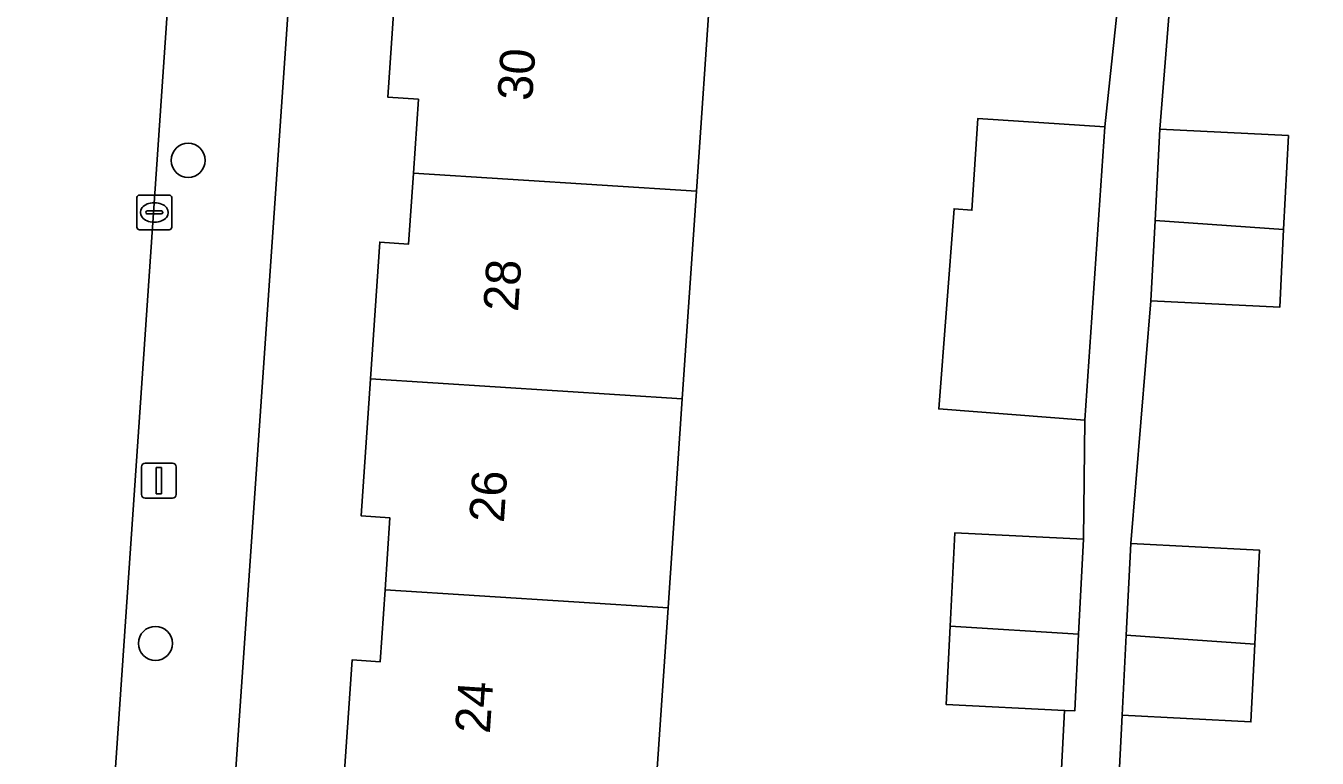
# Model space of a CAD drawing. Extents: x 161848 to 162726, y 385382 to 386521.
# Drawn here: x 162163.48 to 162200.55, y 385538.06 to 385559.08 of the extents above; entities that cross this region are included whole.
import ezdxf

# ---------------------------------------------------------------- set-up
doc = ezdxf.new("R2010")
doc.units = 0
for name, color, linetype in [('IMGEO_Boom', 7, 'Continuous'), ('IMGEO_Erf', 7, 'Continuous'), ('IMGEO_Kolk', 7, 'Continuous'), ('IMGEO_Lichtmast', 7, 'Continuous'), ('IMGEO_Pand', 7, 'Continuous'), ('IMGEO_Pand_nummerreeks', 7, 'Continuous'), ('IMGEO_Rijbaan_lokaal_open', 7, 'Continuous'), ('IMGEO_Voetpad_open', 7, 'Continuous')]:
    doc.layers.add(name, color=color, linetype=linetype)

msp = doc.modelspace()

# ---------------------------------------------------------------- linework, layer by layer
at = {"layer": 'IMGEO_Boom'}
for centre in [(162168.143, 385555.222), (162167.204, 385541.354)]:
    msp.add_circle(centre, 0.489, dxfattribs=at)
at = {"layer": 'IMGEO_Erf'}
for points in [[(162172.594, 385537.139), (162172.849, 385540.88), (162173.652, 385540.825), (162173.793, 385542.892), (162173.934, 385544.958), (162173.109, 385545.015), (162173.377, 385548.946), (162173.644, 385552.875), (162174.469, 385552.819), (162174.608, 385554.855), (162174.752, 385556.977), (162173.874, 385557.037), (162174.143, 385560.983), (162174.411, 385564.925), (162175.255, 385564.868), (162175.394, 385566.905), (162175.534, 385568.968), (162174.708, 385569.025), (162174.97, 385572.867), (162175.556, 385572.827), (162175.575, 385573.109), (162178.486, 385572.911), (162178.639, 385575.119), (162174.67, 385575.382)], [(162220.438, 385572.152), (162212.706, 385572.714), (162200.83, 385573.578), (162200.822, 385573.464), (162200.682, 385571.384), (162200.268, 385565.225), (162200.114, 385562.932), (162196.598, 385563.182), (162196.031, 385556.12), (162199.725, 385555.932), (162199.587, 385553.241), (162199.473, 385551.003), (162195.779, 385551.192), (162195.203, 385544.218), (162198.897, 385544.03), (162198.759, 385541.335), (162198.645, 385539.101), (162194.951, 385539.29), (162194.76, 385535.529)], [(162171.93, 385572.873), (162166.909, 385500)], [(162183.142, 385560.377), (162182.731, 385554.339), (162182.324, 385548.374), (162181.916, 385542.371), (162181.497, 385536.226)], [(162193.033, 385534.21), (162193.3, 385539.431), (162189.897, 385539.605), (162190.012, 385541.852), (162190.149, 385544.533), (162193.843, 385544.344), (162193.881, 385547.762), (162189.688, 385548.084), (162190.128, 385553.83), (162190.638, 385553.79), (162190.812, 385556.427), (162194.451, 385556.187), (162194.817, 385559.603)]]:
    msp.add_lwpolyline(points, dxfattribs=at)
at = {"layer": 'IMGEO_Kolk'}
for p, q in [((162166.671, 385553.3), (162166.671, 385554.152)), ((162166.746, 385554.226), (162167.598, 385554.226)), ((162167.159, 385554.006), (162167.184, 385554.006)), ((162167.672, 385554.152), (162167.672, 385553.3)), ((162166.93, 385553.72), (162166.93, 385553.732)), ((162167.368, 385553.683), (162166.97, 385553.683)), ((162166.973, 385553.769), (162167.371, 385553.769)), ((162167.414, 385553.732), (162167.414, 385553.72)), ((162167.598, 385553.226), (162166.746, 385553.226)), ((162167.182, 385553.446), (162167.157, 385553.446))]:
    msp.add_line(p, q, dxfattribs=at)
for points in [[(162166.671, 385553.3), (162166.671, 385554.152)], [(162166.746, 385554.226), (162167.598, 385554.226)], [(162167.672, 385554.152), (162167.672, 385553.3)], [(162167.598, 385553.226), (162166.746, 385553.226)]]:
    msp.add_lwpolyline(points, dxfattribs=at)
for centre, radius, start, end in [((162166.748, 385554.15), 0.0765, 91.552, 178.448), ((162166.748, 385554.15), 0.0765, 91.552, 178.448), ((162167.596, 385554.15), 0.0765, 1.552, 88.448), ((162167.596, 385554.15), 0.0765, 1.552, 88.448), ((162166.97, 385553.729), 0.0403, 85.8775, 175.7526), ((162166.967, 385553.719), 0.0366, 178.938, 274.7102), ((162167.371, 385553.726), 0.043, 264.8664, 352.4533), ((162167.375, 385553.731), 0.0386, 1.7309, 96.639), ((162166.748, 385553.302), 0.0765, 181.552, 268.448), ((162166.748, 385553.302), 0.0765, 181.552, 268.448), ((162167.596, 385553.302), 0.0765, 271.552, 358.448), ((162167.596, 385553.302), 0.0765, 271.552, 358.448)]:
    msp.add_arc(centre, radius, start, end, dxfattribs=at)
for centre, major_axis, ratio, start_param, end_param in [((162167.158, 385553.726), (-0.387, 0.002), 0.722429, 4.712389, 7.853982), ((162167.183, 385553.726), (-0.39, 0.002), 0.717154, 1.570796, 4.712389)]:
    msp.add_ellipse(centre, major_axis=major_axis, ratio=ratio, start_param=start_param, end_param=end_param, dxfattribs=at)
at = {"layer": 'IMGEO_Lichtmast'}
for p, q in [((162166.906, 385546.526), (162167.696, 385546.526)), ((162167.696, 385546.526), (162166.906, 385546.526)), ((162166.806, 385545.626), (162166.806, 385546.426)), ((162166.806, 385546.426), (162166.806, 385545.626)), ((162167.796, 385546.426), (162167.796, 385545.626)), ((162167.796, 385545.626), (162167.796, 385546.426)), ((162167.696, 385545.526), (162166.906, 385545.526)), ((162166.906, 385545.526), (162167.696, 385545.526))]:
    msp.add_line(p, q, dxfattribs=at)
msp.add_lwpolyline([(162167.226, 385546.401), (162167.376, 385546.401), (162167.376, 385545.651), (162167.226, 385545.651), (162167.226, 385546.401)], dxfattribs=at)
for centre, start, end in [((162166.906, 385546.426), 90, 180), ((162166.906, 385546.426), 90, 180), ((162167.696, 385546.426), 0, 90), ((162167.696, 385546.426), 360, 90), ((162166.906, 385545.626), 180, 270), ((162166.906, 385545.626), 180, 270), ((162167.696, 385545.626), 270, 0), ((162167.696, 385545.626), 270, 0)]:
    msp.add_arc(centre, 0.1, start, end, dxfattribs=at)
at = {"layer": 'IMGEO_Pand'}
for points in [[(162182.731, 385554.339), (162183.142, 385560.377), (162174.143, 385560.983), (162173.874, 385557.037), (162174.752, 385556.977), (162174.608, 385554.855)], [(162194.451, 385556.187), (162190.812, 385556.427), (162190.638, 385553.79), (162190.128, 385553.83), (162189.688, 385548.084), (162193.881, 385547.762)], [(162199.725, 385555.932), (162196.031, 385556.12), (162195.897, 385553.496), (162199.587, 385553.241)], [(162182.324, 385548.374), (162182.731, 385554.339), (162174.608, 385554.855), (162174.469, 385552.819), (162173.644, 385552.875), (162173.377, 385548.946)], [(162195.779, 385551.192), (162199.473, 385551.003), (162199.587, 385553.241), (162195.897, 385553.496)], [(162181.916, 385542.371), (162182.324, 385548.374), (162173.377, 385548.946), (162173.109, 385545.015), (162173.934, 385544.958), (162173.793, 385542.892)], [(162190.012, 385541.852), (162193.703, 385541.615), (162193.843, 385544.344), (162190.149, 385544.533)], [(162195.068, 385541.589), (162198.759, 385541.335), (162198.897, 385544.03), (162195.203, 385544.218)], [(162181.916, 385542.371), (162173.793, 385542.892), (162173.652, 385540.825), (162172.849, 385540.88), (162172.594, 385537.139), (162173.397, 385537.084), (162173.375, 385536.763), (162178.4, 385536.42), (162181.497, 385536.226)], [(162193.703, 385541.615), (162190.012, 385541.852), (162189.897, 385539.605), (162193.3, 385539.431), (162193.591, 385539.416)], [(162198.759, 385541.335), (162195.068, 385541.589), (162194.951, 385539.29), (162198.645, 385539.101)]]:
    msp.add_lwpolyline(points, close=True, dxfattribs=at)
at = {"layer": 'IMGEO_Rijbaan_lokaal_open'}
msp.add_lwpolyline([(162165.753, 385533.321), (162166.136, 385538.907), (162168.482, 385573.131)], dxfattribs=at)
at = {"layer": 'IMGEO_Voetpad_open'}
for points in [[(162168.482, 385573.131), (162166.136, 385538.907), (162165.753, 385533.321), (162163.468, 385500), (162161.151, 385466.324)], [(162164.532, 385465.473), (162164.7, 385467.939), (162166.909, 385500), (162171.93, 385572.873)], [(162194.76, 385535.529), (162194.951, 385539.29), (162195.068, 385541.589), (162195.203, 385544.218), (162195.779, 385551.192), (162195.897, 385553.496), (162196.031, 385556.12), (162196.598, 385563.182)], [(162194.817, 385559.603), (162194.451, 385556.187), (162193.881, 385547.762), (162193.843, 385544.344), (162193.703, 385541.615), (162193.591, 385539.416), (162193.3, 385539.431), (162193.033, 385534.21)]]:
    msp.add_lwpolyline(points, dxfattribs=at)

# ---------------------------------------------------------------- texts
at = {"layer": 'IMGEO_Pand_nummerreeks'}
for s, p in [('30', (162178.015, 385556.915)), ('28', (162177.61, 385550.86)), ('26', (162177.205, 385544.802)), ('24', (162176.8, 385538.747))]:
    msp.add_text(s, height=1, rotation=86.1742, dxfattribs=at).set_placement(p)

doc.saveas('drawing.dxf')
